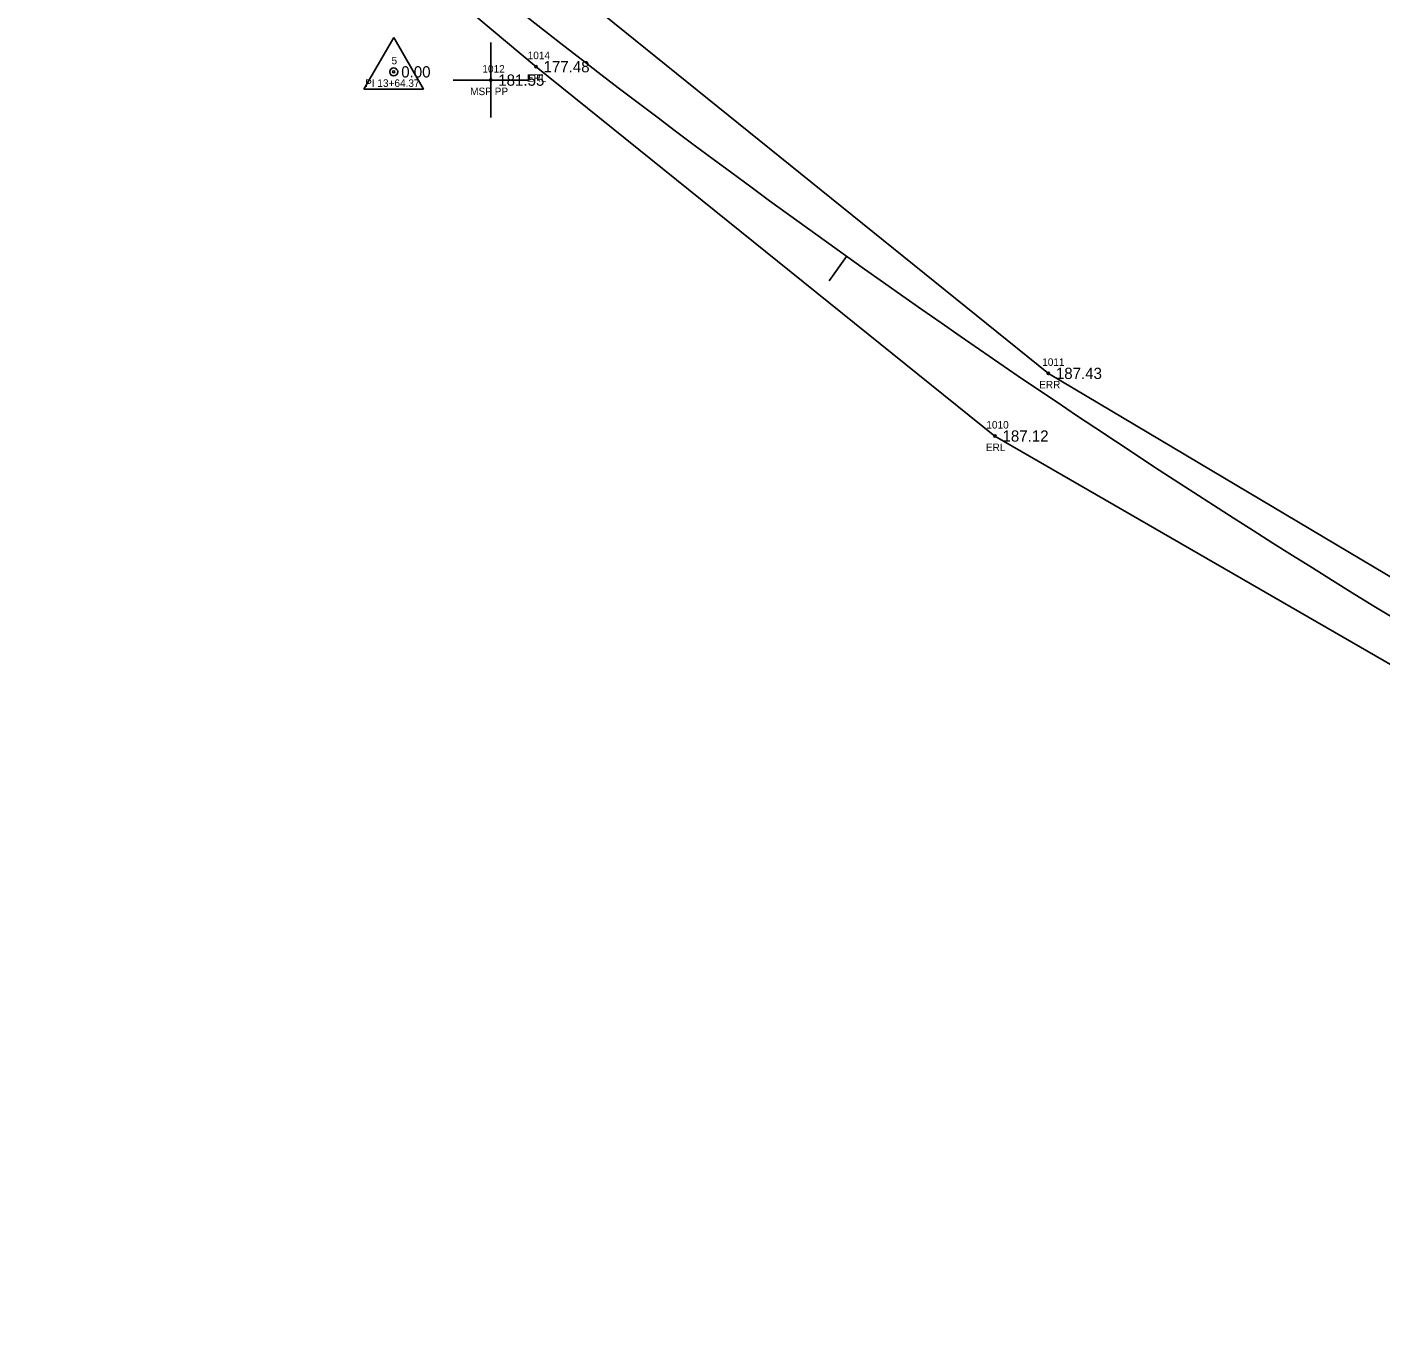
# Model space of a CAD drawing. Extents: x 1970735 to 1971583, y 794736 to 795766.
# Drawn here: x 1971210.6 to 1971390.9, y 794846.6 to 795021.9 of the extents above; entities that cross this region are included whole.
import ezdxf

# ---------------------------------------------------------------- set-up
doc = ezdxf.new("R2010")
doc.units = 0
for name, color, linetype in [('RD_EX_Misc', 7, 'Continuous'), ('RD_EX_Misc_txCode', 7, 'Continuous'), ('RD_EX_Road', 7, 'Continuous'), ('RD_EX_Road_txCode', 7, 'Continuous'), ('RD_EX_TX_Misc_ELEV', 7, 'Continuous'), ('RD_EX_TX_Road_ELEV', 7, 'Continuous'), ('RD_HC_Cl', 7, 'Continuous'), ('RD_HC_Data', 7, 'Continuous'), ('RD_HC_Data_Tic', 7, 'Continuous'), ('RD_HC_Survey_ELEV', 7, 'Continuous'), ('RD_HC_txCode', 7, 'Continuous'), ('RD_SMD_Locator', 7, 'Continuous')]:
    doc.layers.add(name, color=color, linetype=linetype)

msp = doc.modelspace()

# ---------------------------------------------------------------- linework, layer by layer
at = {"layer": 'RD_EX_Misc'}
for p, q in [((1971272.31, 795009.8), (1971272.31, 795019.8)), ((1971267.31, 795014.8), (1971277.31, 795014.8))]:
    msp.add_line(p, q, dxfattribs=at)
at = {"layer": 'RD_EX_Road'}
for points in [[(1971550.5, 794861.13), (1971472.2, 794904.32), (1971401.49, 794943.08), (1971346.58, 794975.73), (1971286.05, 795024.56), (1971217.92, 795079.41), (1971172.76, 795121.06), (1971082.31, 795221.27), (1971017.96, 795288.13), (1970931.75, 795387.33), (1970878.11, 795452.95), (1970856.35, 795489.48), (1970840.29, 795529.45), (1970827.57, 795574.31), (1970814.81, 795635.62), (1970805.04, 795696.13), (1970791.39, 795763.83)], [(1971543.68, 794851.6), (1971507.7, 794872.08), (1971504.76, 794847.96), (1971494.98, 794846.56), (1971488.18, 794883), (1971469.72, 794893.79), (1971395.92, 794934.76), (1971339.47, 794967.38), (1971278.34, 795016.59), (1971212.1, 795072.1), (1971165.04, 795113.96), (1971074.42, 795213.48), (1971010.42, 795281.48), (1970922.49, 795383.19), (1970882.25, 795365.41), (1970854.66, 795404.07), (1970871.45, 795443.76), (1970844.39, 795483.83), (1970828.93, 795526.65), (1970817.76, 795568.61), (1970806.82, 795600.57), (1970787.72, 795602.49), (1970770.58, 795591.56)]]:
    msp.add_lwpolyline(points, dxfattribs=at)
at = {"layer": 'RD_HC_Cl'}
msp.add_arc((1972021.16, 795972.61), 1206.22, 221.98645, 240.95681, dxfattribs=at)
at = {"layer": 'RD_HC_Data'}
for p, q in [((1971255.42, 795013.61), (1971259.39, 795020.49)), ((1971259.39, 795020.49), (1971263.36, 795013.61)), ((1971255.42, 795013.61), (1971263.36, 795013.61))]:
    msp.add_line(p, q, dxfattribs=at)
msp.add_circle((1971259.39, 795015.9), 0.529, dxfattribs=at)
at = {"layer": 'RD_HC_Data_Tic'}
msp.add_line((1971319.7, 794991.32), (1971317.37, 794988.06), dxfattribs=at)
at = {"layer": 'RD_SMD_Locator'}
for centre in [(1971259.39, 795015.9), (1971278.34, 795016.59), (1971272.31, 795014.8), (1971346.58, 794975.73), (1971339.47, 794967.38)]:
    msp.add_circle(centre, 0.15, dxfattribs=at)

# ---------------------------------------------------------------- texts
at = {"layer": 'RD_EX_Misc_txCode'}
for s, p in [('1012', (1971271.2, 795015.8)), ('MSP PP', (1971269.57, 795012.8))]:
    msp.add_text(s, height=1, dxfattribs=at).set_placement(p)
at = {"layer": 'RD_EX_Road_txCode'}
for s, p in [('1014', (1971277.23, 795017.59)), ('ERL', (1971277.13, 795014.59)), ('1011', (1971345.76, 794976.73)), ('ERR', (1971345.35, 794973.73)), ('1010', (1971338.32, 794968.38)), ('ERL', (1971338.26, 794965.38))]:
    msp.add_text(s, height=1, dxfattribs=at).set_placement(p)
at = {"layer": 'RD_EX_TX_Misc_ELEV'}
msp.add_text('181.55', height=1.5, dxfattribs=at).set_placement((1971273.31, 795014.05))
at = {"layer": 'RD_EX_TX_Road_ELEV'}
for s, p in [('177.48', (1971279.34, 795015.84)), ('187.43', (1971347.58, 794974.98)), ('187.12', (1971340.47, 794966.63))]:
    msp.add_text(s, height=1.5, dxfattribs=at).set_placement(p)
at = {"layer": 'RD_HC_Survey_ELEV'}
msp.add_text('0.00', height=1.5, dxfattribs=at).set_placement((1971260.39, 795015.15))
at = {"layer": 'RD_HC_txCode'}
for s, p in [('5', (1971259.1, 795016.9)), ('PI 13+64.37', (1971255.58, 795013.9))]:
    msp.add_text(s, height=1, dxfattribs=at).set_placement(p)

doc.saveas('drawing.dxf')
